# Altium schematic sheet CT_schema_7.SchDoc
size 402 x 220 mm
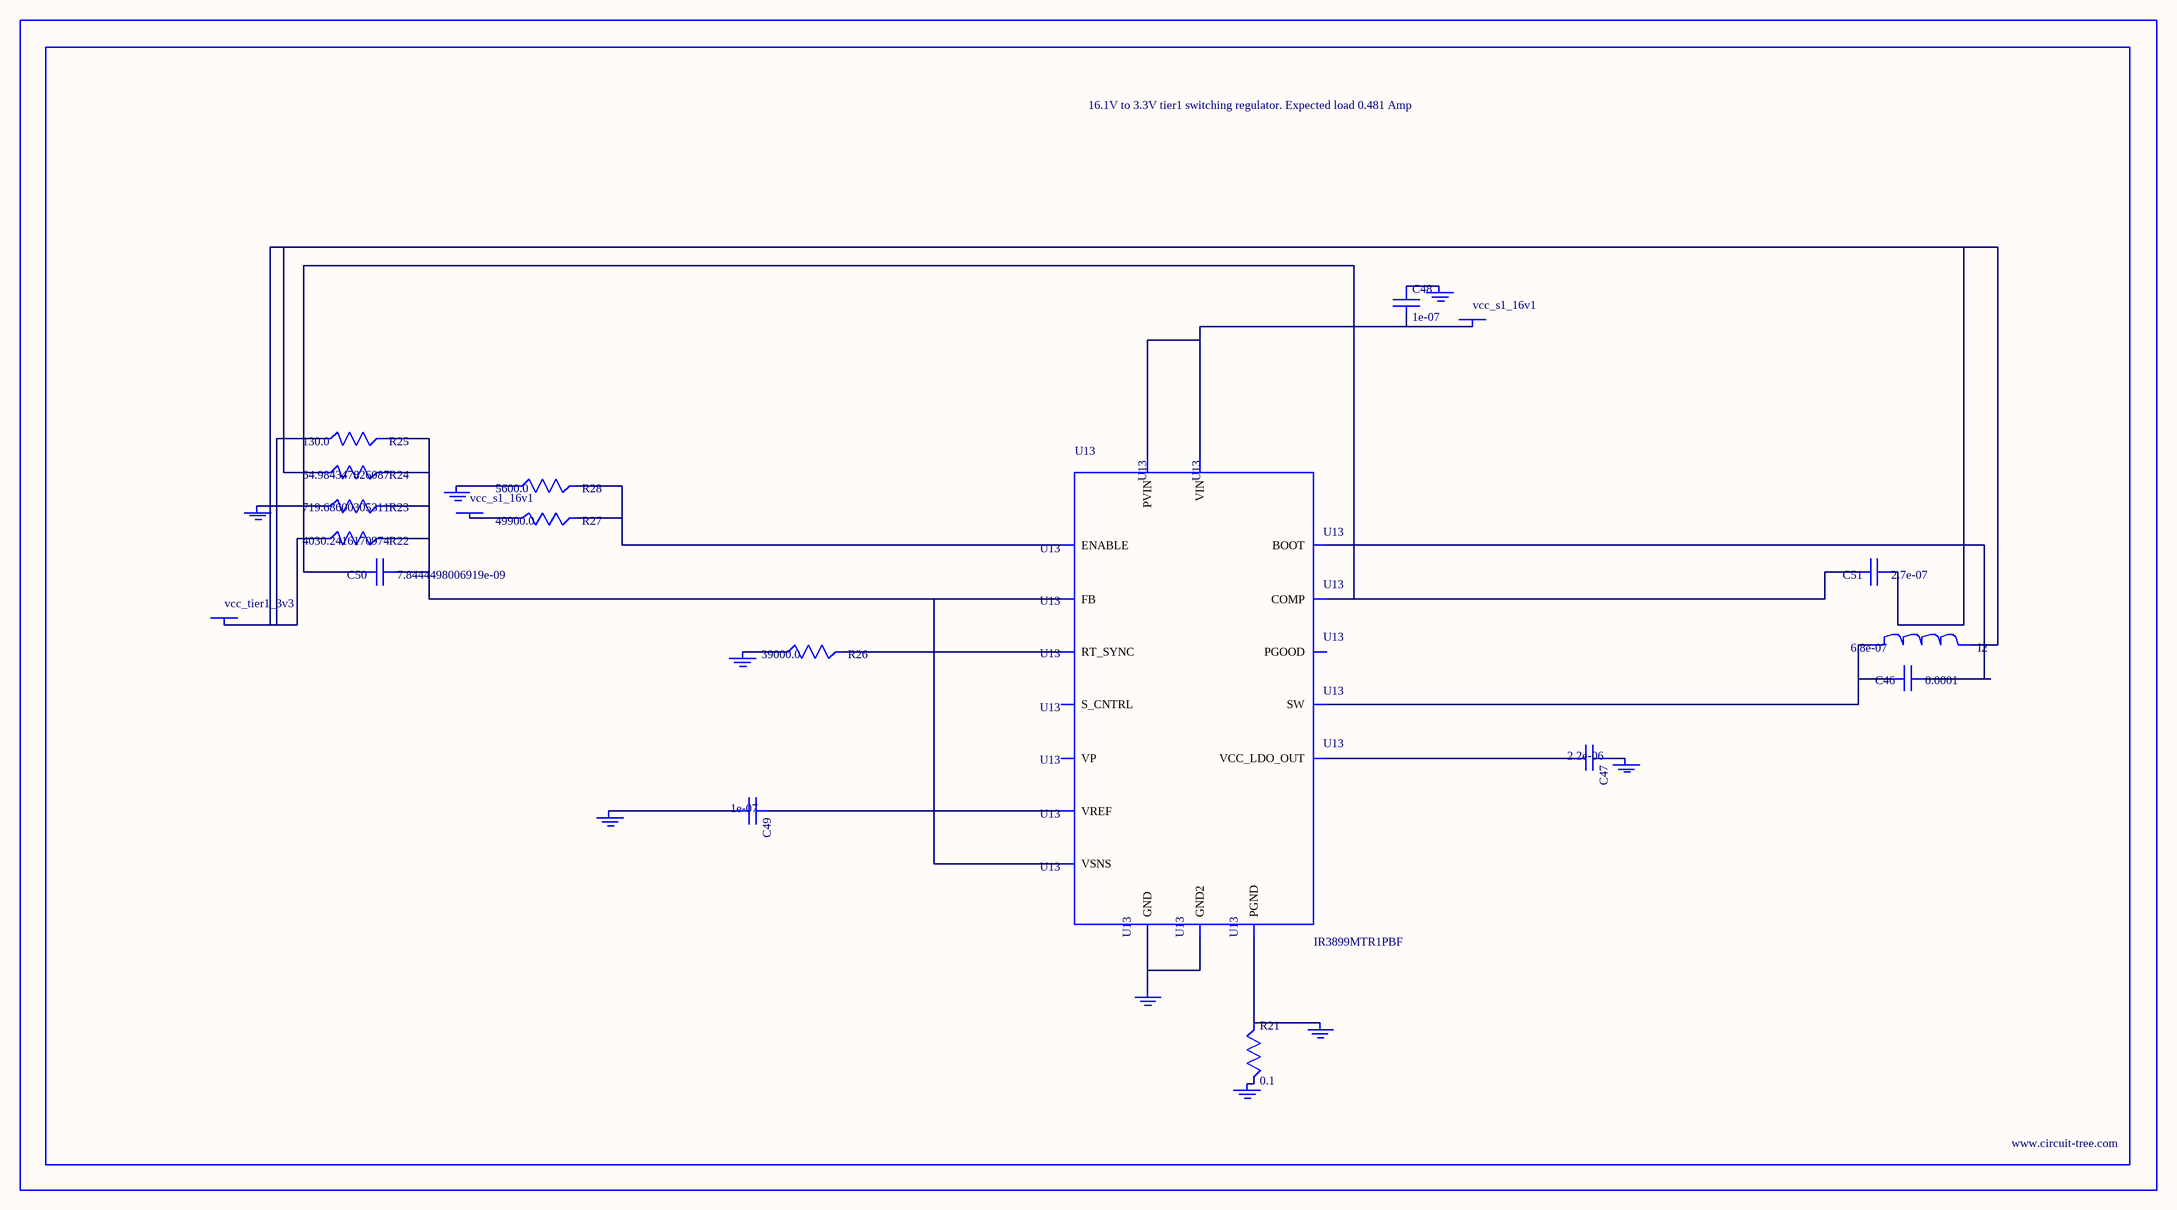
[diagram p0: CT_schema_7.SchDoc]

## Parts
BORDER6  (no value)
C46  0.0001  [C1210]
C47  2.2e-06  [C0603]
C48  1e-07  [C0402]
C49  1e-07  [C0402]
C50  7.8444498006919e-09  [R0603]
C51  2.7e-07  [C0603]
GND_INSTANCE_6_0  (no value)
GND_INSTANCE_6_1  (no value)
GND_INSTANCE_6_2  (no value)
GND_INSTANCE_6_3  (no value)
GND_INSTANCE_6_4  (no value)
GND_INSTANCE_6_5  (no value)
GND_INSTANCE_6_6  (no value)
GND_INSTANCE_6_7  (no value)
GND_INSTANCE_6_8  (no value)
I2  6.8e-07  [IND25X25CZ]
POWER_INSTANCE_6_0  vcc_s1_16v1
POWER_INSTANCE_6_1  vcc_s1_16v1
POWER_INSTANCE_6_2  vcc_tier1_3v3
R21  0.1  [R0603]
R22  4030.2416170974  [R0603]
R23  719.68600305311  [R0603]
R24  64.984347826087  [R0603]
R25  130.0  [R0603]
R26  39000.0  [R0603]
R27  49900.0  [R0603]
R28  5600.0  [R0603]
U13  IR3899MTR1PBF  [IR3899MTR1PBF]

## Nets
NetC46_1: C46.1 U13.14(BOOT)
NetC46_2: C46.2 I2.1 U13.12(SW)
NetC47_1: C47.1 GND_INSTANCE_6_4.0(GND)
NetC47_2: C47.2 U13.10(VCC_LDO_OUT)
NetC48_1: C48.1 GND_INSTANCE_6_3.0(GND)
NetC48_2: C48.2 POWER_INSTANCE_6_0.0(PWR) U13.9(VIN) U13.13(PVIN)
NetC49_1: C49.1 U13.2(VREF)
NetC49_2: C49.2 GND_INSTANCE_6_1.0(GND)
NetC50_1: C50.1 R22.2 R23.2 R24.2 R25.2 U13.1(FB) U13.8(VSNS)
NetC50_2: C50.2 C51.2 U13.3(COMP)
NetC51_1: C51.1 I2.2 POWER_INSTANCE_6_2.0(PWR) R22.1 R24.1 R25.1
NetGND_INSTANCE_6_0_0: GND_INSTANCE_6_0.0(GND) R23.1
NetGND_INSTANCE_6_2_0: GND_INSTANCE_6_2.0(GND) R26.1
NetGND_INSTANCE_6_5_0: GND_INSTANCE_6_5.0(GND) R21.2
NetGND_INSTANCE_6_6_0: GND_INSTANCE_6_6.0(GND) R21.1 U13.11(PGND)
NetGND_INSTANCE_6_7_0: GND_INSTANCE_6_7.0(GND) R28.1
NetGND_INSTANCE_6_8_0: GND_INSTANCE_6_8.0(GND) U13.4(GND) U13.17(GND2)
NetPOWER_INSTANCE_6_1_0: POWER_INSTANCE_6_1.0(PWR) R27.1
NetR26_2: R26.2 U13.5(RT_SYNC)
NetR27_2: R27.2 R28.2 U13.15(ENABLE)

Not connected (* = marked no-connect by the designer): U13 6(S_CNTRL) 7(PGOOD) 16(VP)

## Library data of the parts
BORDER6 = BORDER_PAGE6
C46 = GRM32ER61A107ME20L
C47 = C0603C225K8RACTU
C48 C49 = C0402C104K3RACTU
C50 = C50
C51 = C0603C274K3RAC
GND_INSTANCE_6_0-GND_INSTANCE_6_8 = GND
I2 = IHLP2525CZERR68M01
POWER_INSTANCE_6_0-POWER_INSTANCE_6_2 = PWR
R21 = ERJ-3RSFR10V
R22 = R22
R23 = R23
R24 = R24
R25 = RC0603JR-07130RL
R26 = RC0603JR-0739KL
R27 = RC0603FR-0749K9
R28 = RC0603JR-075K6L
